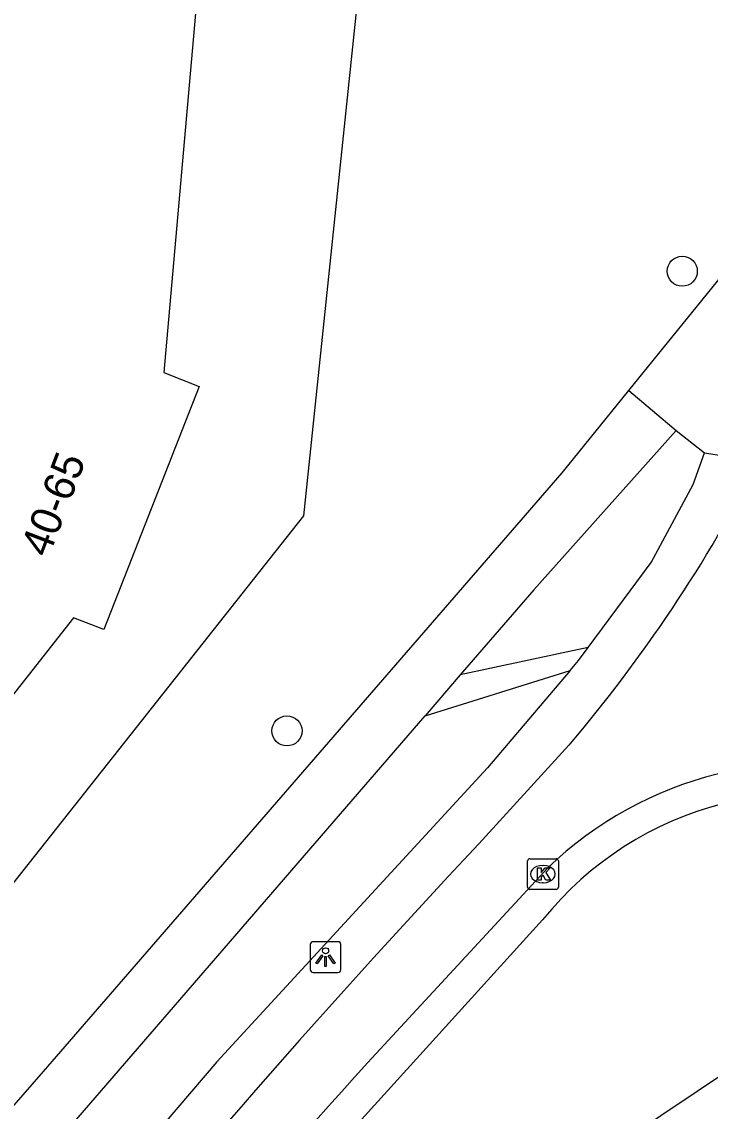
# Model space of a CAD drawing. Extents: x 160304 to 160954, y 383686 to 384161.
# Drawn here: x 160858.01 to 160880.35, y 383807.15 to 383842.52 of the extents above; entities that cross this region are included whole.
import ezdxf

# ---------------------------------------------------------------- set-up
doc = ezdxf.new("R2010")
doc.units = 0
for name, color, linetype in [('IMGEO_Boom', 7, 'Continuous'), ('IMGEO_Fietspad_open', 7, 'Continuous'), ('IMGEO_Groenvoorziening', 7, 'Continuous'), ('IMGEO_Kolk', 7, 'Continuous'), ('IMGEO_Lichtpunt', 7, 'Continuous'), ('IMGEO_Pand', 7, 'Continuous'), ('IMGEO_Pand_nummerreeks', 7, 'Continuous'), ('IMGEO_Voetpad_halfverhard', 7, 'Continuous'), ('IMGEO_Voetpad_open', 7, 'Continuous')]:
    doc.layers.add(name, color=color, linetype=linetype)

msp = doc.modelspace()

# ---------------------------------------------------------------- linework, layer by layer
at = {"layer": 'IMGEO_Boom'}
for centre in [(160879.447, 383834.418), (160866.617, 383819.497)]:
    msp.add_circle(centre, 0.489, dxfattribs=at)
at = {"layer": 'IMGEO_Fietspad_open'}
for points in [[(160875.771, 383819.031), (160872.844, 383815.828)], [(160869.242, 383808.735), (160875.081, 383815.051)]]:
    msp.add_lwpolyline(points, dxfattribs=at)
for centre, radius, start, end in [((160838.055, 383850.957), 49.415, 319.7524, 332.6382), ((160883.569, 383806.203), 12.261, 74.4294, 133.8101), ((161101.821, 383600.979), 313.991, 136.82328, 145.22029), ((161080.422, 383618.144), 284.468, 137.93366, 146.11352)]:
    msp.add_arc(centre, radius, start, end, dxfattribs=at)
at = {"layer": 'IMGEO_Groenvoorziening'}
msp.add_lwpolyline([(160857.274, 383875.816), (160862.472, 383878.595), (160870.895, 383862.33), (160867.154, 383826.483), (160854.767, 383810.821), (160851.843, 383813.196)], dxfattribs=at)
at = {"layer": 'IMGEO_Kolk'}
for p, q in [((160874.424, 383814.422), (160874.424, 383815.274)), ((160874.499, 383815.348), (160875.351, 383815.348)), ((160875.425, 383815.274), (160875.425, 383814.422)), ((160874.912, 383815.128), (160874.937, 383815.128)), ((160874.935, 383814.568), (160874.91, 383814.568)), ((160875.351, 383814.348), (160874.499, 383814.348))]:
    msp.add_line(p, q, dxfattribs=at)
for points in [[(160874.424, 383814.422), (160874.424, 383815.274)], [(160874.499, 383815.348), (160875.351, 383815.348)], [(160875.425, 383815.274), (160875.425, 383814.422)], [(160874.745, 383815.048), (160874.868, 383815.048), (160874.868, 383814.897), (160874.998, 383815.048), (160875.162, 383815.048), (160875.016, 383814.897), (160875.169, 383814.648), (160875.017, 383814.648), (160874.932, 383814.812), (160874.868, 383814.745), (160874.868, 383814.648), (160874.745, 383814.648), (160874.745, 383815.048)], [(160875.351, 383814.348), (160874.499, 383814.348)]]:
    msp.add_lwpolyline(points, dxfattribs=at)
for centre, start, end in [((160874.501, 383815.272), 91.552, 178.448), ((160874.501, 383815.272), 91.552, 178.448), ((160875.349, 383815.272), 1.552, 88.448), ((160875.349, 383815.272), 1.552, 88.448), ((160874.501, 383814.424), 181.552, 268.448), ((160874.501, 383814.424), 181.552, 268.448), ((160875.349, 383814.424), 271.552, 358.448), ((160875.349, 383814.424), 271.552, 358.448)]:
    msp.add_arc(centre, 0.0765, start, end, dxfattribs=at)
for centre, major_axis, ratio, start_param, end_param in [((160874.911, 383814.848), (-0.387, 0.002), 0.722429, 4.712389, 7.853982), ((160874.936, 383814.848), (-0.39, 0.002), 0.717154, 1.570796, 4.712389)]:
    msp.add_ellipse(centre, major_axis=major_axis, ratio=ratio, start_param=start_param, end_param=end_param, dxfattribs=at)
at = {"layer": 'IMGEO_Lichtpunt'}
for p, q in [((160867.371, 383812.559), (160867.371, 383811.752)), ((160867.371, 383812.559), (160867.371, 383811.752)), ((160868.273, 383812.654), (160867.465, 383812.654)), ((160868.273, 383812.654), (160867.465, 383812.654)), ((160868.367, 383811.752), (160868.367, 383812.559)), ((160868.367, 383811.752), (160868.367, 383812.559)), ((160867.465, 383811.658), (160868.273, 383811.658)), ((160867.465, 383811.658), (160868.273, 383811.658))]:
    msp.add_line(p, q, dxfattribs=at)
for points in [[(160867.745, 383812.223), (160867.784, 383812.195), (160867.596, 383811.933), (160867.558, 383811.96), (160867.745, 383812.223)], [(160867.847, 383812.175), (160867.894, 383812.175), (160867.894, 383811.853), (160867.847, 383811.853), (160867.847, 383812.175)], [(160867.957, 383812.195), (160867.995, 383812.222), (160868.182, 383811.96), (160868.143, 383811.932), (160867.957, 383812.195)]]:
    msp.add_lwpolyline(points, dxfattribs=at)
msp.add_circle((160867.87, 383812.357), 0.0994, dxfattribs=at)
for centre, start, end in [((160867.465, 383812.559), 90, 180), ((160867.465, 383812.559), 90, 180), ((160868.273, 383812.559), 0, 90), ((160868.273, 383812.559), 0, 90), ((160867.465, 383811.752), 180, 270), ((160867.465, 383811.752), 180, 270), ((160868.273, 383811.752), 270, 0), ((160868.273, 383811.752), 270, 360)]:
    msp.add_arc(centre, 0.0946, start, end, dxfattribs=at)
at = {"layer": 'IMGEO_Pand'}
msp.add_lwpolyline([(160863.738, 383843.778), (160862.62, 383831.129), (160863.763, 383830.681), (160860.673, 383822.784), (160859.69, 383823.168), (160851.843, 383813.196)], dxfattribs=at)
at = {"layer": 'IMGEO_Voetpad_halfverhard'}
for points in [[(160876.395, 383822.205), (160872.244, 383821.313)], [(160871.102, 383819.99), (160875.807, 383821.459)]]:
    msp.add_lwpolyline(points, dxfattribs=at)
at = {"layer": 'IMGEO_Voetpad_open'}
for points in [[(160877.717, 383830.549), (160881.2, 383834.841), (160882.012, 383836.593), (160882.318, 383837.458), (160882.546, 383838.346), (160882.694, 383839.251), (160882.76, 383840.166), (160882.75, 383840.973), (160882.015, 383844.961), (160869.45, 383895.902)], [(160847.919, 383796.056), (160858.712, 383808.442), (160875.547, 383827.875), (160877.717, 383830.549)], [(160877.717, 383830.549), (160879.254, 383829.246)], [(160879.254, 383829.246), (160874.628, 383824.072), (160872.244, 383821.313)], [(160879.254, 383829.246), (160880.164, 383828.519)], [(160876.395, 383822.205), (160878.434, 383824.961), (160879.799, 383827.494), (160880.164, 383828.519)], [(160880.164, 383828.519), (160881.941, 383828.246)], [(160875.807, 383821.459), (160876.081, 383821.782), (160876.395, 383822.205)], [(160875.807, 383821.459), (160873.125, 383818.297), (160864.338, 383808.756), (160858.767, 383802.234), (160853.84, 383796.208), (160847.633, 383788.041), (160844.965, 383784.351), (160841.939, 383779.888), (160839.455, 383776.223), (160835.377, 383769.709), (160831.252, 383762.844), (160822.902, 383750), (160820.261, 383745.938)], [(160872.244, 383821.313), (160871.102, 383819.99)], [(160840.438, 383784.74), (160849.874, 383795.418), (160871.102, 383819.99)], [(160860.248, 383796.503), (160868.835, 383806.658), (160874.916, 383813.366)], [(160885.585, 383811.414), (160883.919, 383810.362), (160881.079, 383808.556), (160877.609, 383806.234), (160876.088, 383805.064), (160870.625, 383800.581), (160866.383, 383796.809), (160864.404, 383794.743), (160861.952, 383791.983), (160861.38, 383791.263)]]:
    msp.add_lwpolyline(points, dxfattribs=at)
msp.add_arc((160883.518, 383806.436), 11.046, 67.8486, 141.1449, dxfattribs=at)

# ---------------------------------------------------------------- texts
at = {"layer": 'IMGEO_Pand_nummerreeks'}
msp.add_text('40-65', height=1, rotation=69.0832, dxfattribs=at).set_placement((160858.879, 383825.09))

doc.saveas('drawing.dxf')
